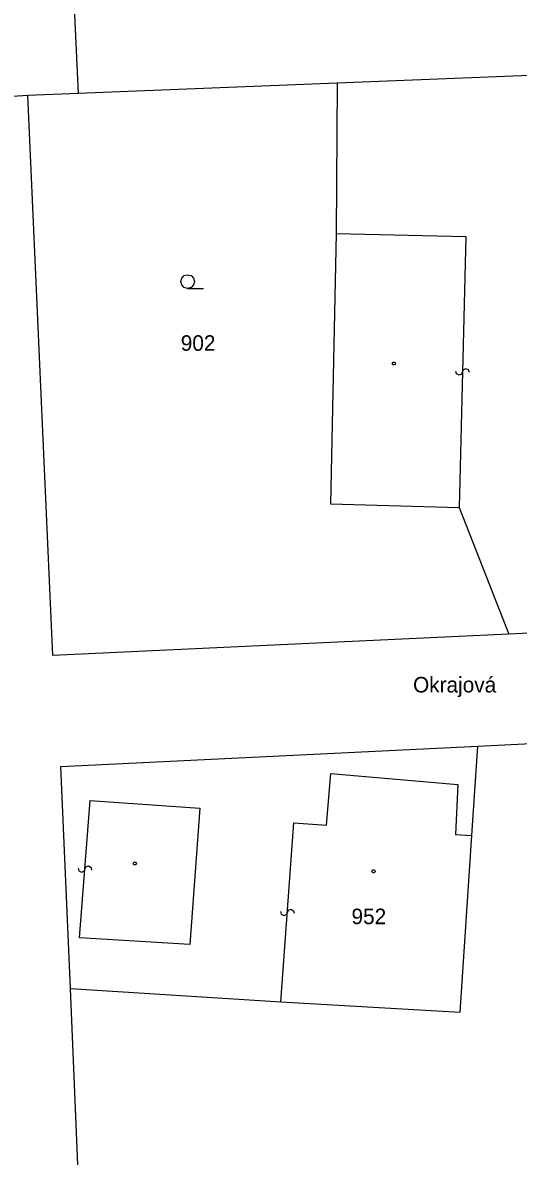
# Model space of a CAD drawing. Extents: x -456675 to -456278, y -1112395 to -1112217.
# Drawn here: x -456625.5 to -456598.3, y -1112328.7 to -1112266.7 of the extents above; entities that cross this region are included whole.
import ezdxf

# ---------------------------------------------------------------- set-up
doc = ezdxf.new("R2010")
doc.units = 0
doc.layers.add('Katastralni_mapa', color=7, linetype='Continuous')

msp = doc.modelspace()

# ---------------------------------------------------------------- linework, layer by layer
at = {"layer": 'Katastralni_mapa'}
for points in [[(-456624.5, -1112225.87), (-456622.42, -1112270.58)], [(-456594.03, -1112269.44), (-456608.25, -1112270.01)], [(-456608.25, -1112270.01), (-456622.42, -1112270.58)], [(-456608.25, -1112270.01), (-456608.31, -1112278.24)], [(-456625.18, -1112270.69), (-456628.25, -1112270.88)], [(-456622.42, -1112270.58), (-456625.18, -1112270.69)], [(-456623.8, -1112301.33), (-456625.18, -1112270.69)], [(-456608.31, -1112278.24), (-456608.61, -1112293.03)], [(-456608.31, -1112278.24), (-456601.21, -1112278.41)], [(-456601.21, -1112278.41), (-456601.57, -1112293.22)], [(-456616.43, -1112281.24), (-456616.62, -1112281.19), (-456616.755, -1112281.05), (-456616.805, -1112280.865), (-456616.755, -1112280.68), (-456616.62, -1112280.54), (-456616.43, -1112280.49), (-456616.24, -1112280.54), (-456616.105, -1112280.68), (-456616.055, -1112280.865), (-456616.105, -1112281.05), (-456616.24, -1112281.19), (-456616.43, -1112281.24), (-456615.555, -1112281.24)], [(-456601.016, -1112285.849), (-456601.062, -1112285.698), (-456601.215, -1112285.634), (-456601.352, -1112285.701), (-456601.443, -1112285.939), (-456601.585, -1112285.995), (-456601.728, -1112285.922), (-456601.764, -1112285.781)], [(-456608.61, -1112293.03), (-456601.57, -1112293.22)], [(-456601.57, -1112293.22), (-456598.86, -1112300.15)], [(-456598.86, -1112300.15), (-456623.8, -1112301.33)], [(-456593.04, -1112299.87), (-456598.86, -1112300.15)], [(-456600.55, -1112306.28), (-456578.75, -1112305.2)], [(-456623.36, -1112307.4), (-456600.55, -1112306.28)], [(-456600.88, -1112311.18), (-456600.55, -1112306.28)], [(-456622.84, -1112319.54), (-456623.36, -1112307.4)], [(-456608.83, -1112310.61), (-456608.59, -1112307.78)], [(-456608.59, -1112307.78), (-456601.65, -1112308.39)], [(-456601.65, -1112308.39), (-456601.78, -1112311.12)], [(-456622.34, -1112316.77), (-456621.77, -1112309.25)], [(-456621.77, -1112309.25), (-456615.76, -1112309.68)], [(-456615.76, -1112309.68), (-456616.31, -1112317.13)], [(-456611.34, -1112320.27), (-456610.62, -1112310.48)], [(-456610.62, -1112310.48), (-456608.83, -1112310.61)], [(-456601.78, -1112311.12), (-456600.88, -1112311.18)], [(-456601.53, -1112320.83), (-456600.88, -1112311.18)], [(-456622.427, -1112312.957), (-456622.388, -1112313.11), (-456622.238, -1112313.182), (-456622.099, -1112313.122), (-456621.996, -1112312.889), (-456621.852, -1112312.84), (-456621.712, -1112312.92), (-456621.683, -1112313.063)], [(-456611.352, -1112315.323), (-456611.313, -1112315.476), (-456611.163, -1112315.547), (-456611.023, -1112315.487), (-456610.921, -1112315.254), (-456610.777, -1112315.204), (-456610.637, -1112315.285), (-456610.608, -1112315.427)], [(-456616.31, -1112317.13), (-456622.34, -1112316.77)], [(-456622.01, -1112339.26), (-456622.84, -1112319.54)], [(-456622.84, -1112319.54), (-456611.34, -1112320.27)], [(-456611.34, -1112320.27), (-456601.53, -1112320.83)]]:
    msp.add_lwpolyline(points, dxfattribs=at)
for points in [[(-456605.105, -1112285.275), (-456605.06, -1112285.35), (-456605.105, -1112285.425), (-456605.195, -1112285.425), (-456605.24, -1112285.35), (-456605.195, -1112285.275)], [(-456619.275, -1112312.625), (-456619.23, -1112312.7), (-456619.275, -1112312.775), (-456619.365, -1112312.775), (-456619.41, -1112312.7), (-456619.365, -1112312.625)], [(-456606.26, -1112313.045), (-456606.21, -1112313.055), (-456606.185, -1112313.1), (-456606.175, -1112313.13), (-456606.185, -1112313.175), (-456606.225, -1112313.21), (-456606.26, -1112313.215), (-456606.305, -1112313.2), (-456606.335, -1112313.17), (-456606.345, -1112313.13), (-456606.335, -1112313.085), (-456606.295, -1112313.05)]]:
    msp.add_lwpolyline(points, close=True, dxfattribs=at)

# ---------------------------------------------------------------- texts
for s, p in [('902', (-456616.806, -1112284.655)), ('Okrajová', (-456604.099, -1112303.348)), ('952', (-456607.465, -1112316.024))]:
    msp.add_text(s, height=0.85, dxfattribs=at).set_placement(p)

doc.saveas('drawing.dxf')
